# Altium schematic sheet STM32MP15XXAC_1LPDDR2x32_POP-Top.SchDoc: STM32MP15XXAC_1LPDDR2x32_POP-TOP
size A4; Date: Not used; ApprovedBy: Not used; CheckedBy: Not used; Author: Not used; CompanyName: STMicroelectronics; DrawnBy: Not used; Engineer: Not used; Organization: Not used; Address1: Not used; Address2: Not used; Address3: Not used; Address4: Not used; DocumentNumber: Not used; Revision: Not used; SheetNumber: 2; SheetTotal: 7
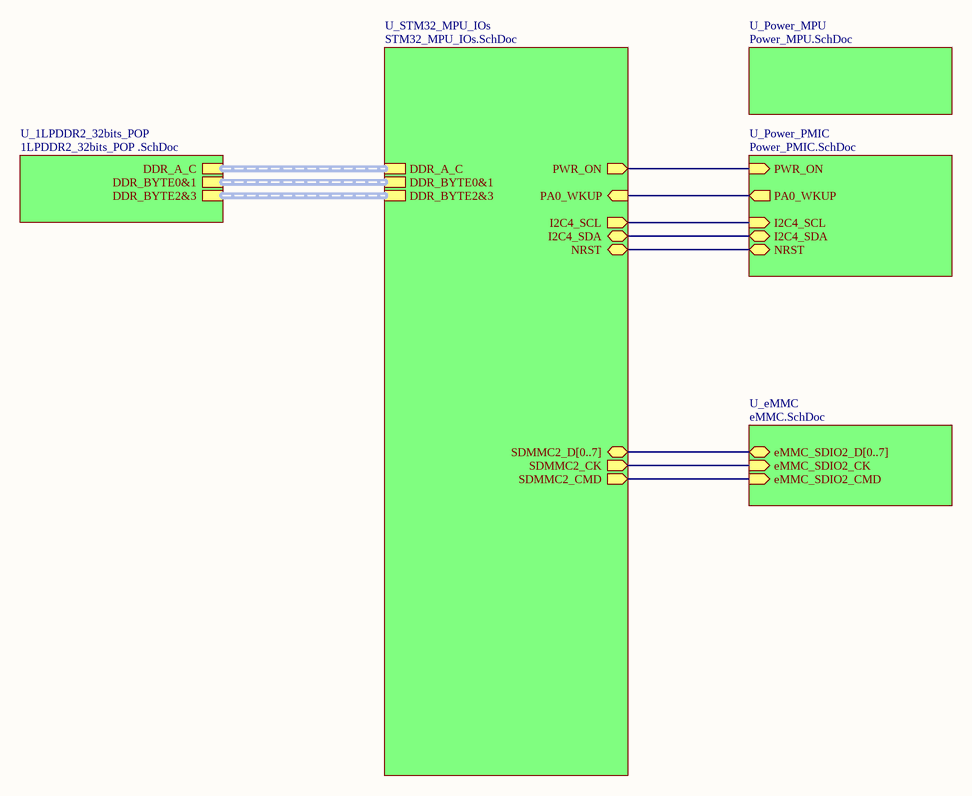
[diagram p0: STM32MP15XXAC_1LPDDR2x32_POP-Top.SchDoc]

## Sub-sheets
U_1LPDDR2_32bits_POP  = 1LPDDR2_32bits_POP .SchDoc: DDR_BYTE0&1 (harness DDR_BYTE_0&1), DDR_BYTE2&3 (harness DDR_BYTE_2&3), DDR_A_C (harness DDR_A_C)
U_eMMC = eMMC.SchDoc: eMMC_SDIO2_CK (in), eMMC_SDIO2_D[0..7] (bidir), eMMC_SDIO2_CMD (in)
U_Power_MPU = Power_MPU.SchDoc: no entries
U_Power_PMIC = Power_PMIC.SchDoc: I2C4_SDA (bidir), I2C4_SCL (in), PA0_WKUP (out), NRST (bidir), PWR_ON (in)
U_STM32_MPU_IOs = STM32_MPU_IOs.SchDoc: PA0_WKUP (in), NRST (bidir), PWR_ON (out), I2C4_SCL (out), I2C4_SDA (bidir), DDR_BYTE0&1 (harness DDR_BYTE_0&1), DDR_A_C (harness DDR_A_C), SDMMC2_D[0..7] (bidir), SDMMC2_CMD (out), SDMMC2_CK (out), DDR_BYTE2&3 (harness DDR_BYTE_2&3)

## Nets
(unnamed): sheet U_Power_PMIC/I2C4_SDA, sheet U_STM32_MPU_IOs/I2C4_SDA
(unnamed): sheet U_Power_PMIC/I2C4_SCL, sheet U_STM32_MPU_IOs/I2C4_SCL  [a separate net that carries the same name]
(unnamed): sheet U_Power_PMIC/PA0_WKUP, sheet U_STM32_MPU_IOs/PA0_WKUP  [a separate net that carries the same name]
(unnamed): sheet U_Power_PMIC/NRST, sheet U_STM32_MPU_IOs/NRST  [a separate net that carries the same name]
(unnamed): sheet U_Power_PMIC/PWR_ON, sheet U_STM32_MPU_IOs/PWR_ON  [a separate net that carries the same name]
(unnamed): sheet U_eMMC/eMMC_SDIO2_CK, sheet U_STM32_MPU_IOs/SDMMC2_CK  [a separate net that carries the same name]
(unnamed): sheet U_eMMC/eMMC_SDIO2_CMD, sheet U_STM32_MPU_IOs/SDMMC2_CMD  [a separate net that carries the same name]

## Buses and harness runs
bus sheet U_eMMC/eMMC_SDIO2_D[0..7] = sheet U_STM32_MPU_IOs/SDMMC2_D[0..7]
harness sheet U_1LPDDR2_32bits_POP /DDR_A_C = sheet U_STM32_MPU_IOs/DDR_A_C
harness sheet U_1LPDDR2_32bits_POP /DDR_BYTE0&1 = sheet U_STM32_MPU_IOs/DDR_BYTE0&1
harness sheet U_1LPDDR2_32bits_POP /DDR_BYTE2&3 = sheet U_STM32_MPU_IOs/DDR_BYTE2&3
